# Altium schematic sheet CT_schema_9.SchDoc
size 281 x 153 mm
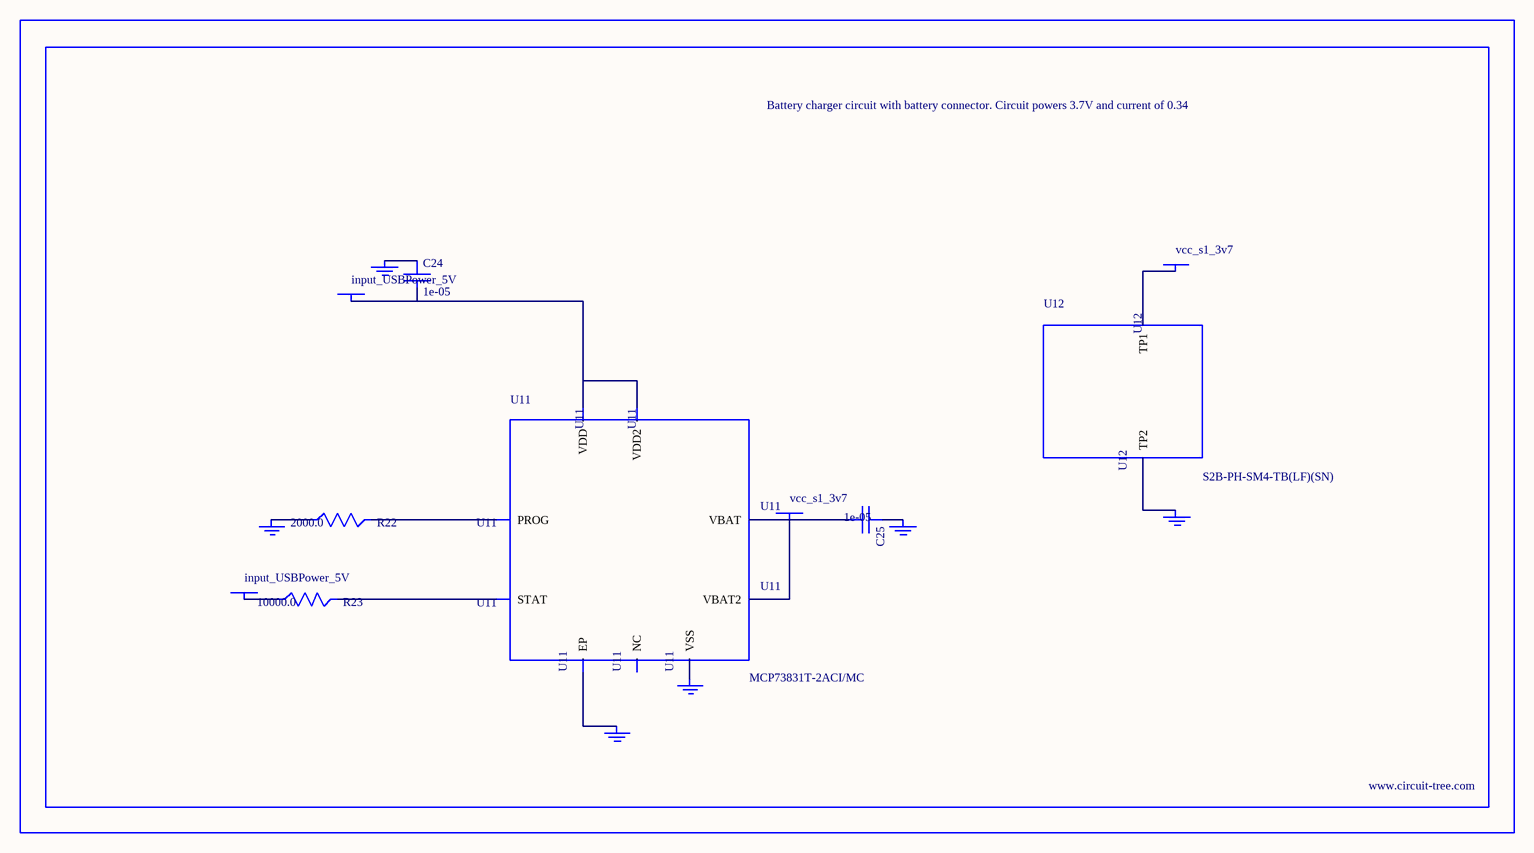
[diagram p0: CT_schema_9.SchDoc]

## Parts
BORDER8  (no value)
C24  1e-05  [C1206]
C25  1e-05  [C1206]
GND_INSTANCE_8_0  (no value)
GND_INSTANCE_8_1  (no value)
GND_INSTANCE_8_2  (no value)
GND_INSTANCE_8_3  (no value)
GND_INSTANCE_8_4  (no value)
GND_INSTANCE_8_5  (no value)
POWER_INSTANCE_8_0  input_USBPower_5V
POWER_INSTANCE_8_1  input_USBPower_5V
POWER_INSTANCE_8_2  vcc_s1_3v7
POWER_INSTANCE_8_3  vcc_s1_3v7
R22  2000.0  [R0603]
R23  10000.0  [R0603]
U11  MCP73831T-2ACI/MC  [DFN8_2X3MC]
U12  S2B-PH-SM4-TB(LF)(SN)  [JST-2-SMD]

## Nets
NetC24_1: C24.1 GND_INSTANCE_8_0.0(GND)
NetC24_2: C24.2 POWER_INSTANCE_8_0.0(PWR) U11.1(VDD) U11.2(VDD2)
NetC25_1: C25.1 GND_INSTANCE_8_1.0(GND)
NetC25_2: C25.2 POWER_INSTANCE_8_2.0(PWR) U11.3(VBAT) U11.4(VBAT2)
NetGND_INSTANCE_8_2_0: GND_INSTANCE_8_2.0(GND) R22.1
NetGND_INSTANCE_8_3_0: GND_INSTANCE_8_3.0(GND) U11.9(EP)
NetGND_INSTANCE_8_4_0: GND_INSTANCE_8_4.0(GND) U11.6(VSS)
NetGND_INSTANCE_8_5_0: GND_INSTANCE_8_5.0(GND) U12.2(TP2)
NetPOWER_INSTANCE_8_1_0: POWER_INSTANCE_8_1.0(PWR) R23.1
NetPOWER_INSTANCE_8_3_0: POWER_INSTANCE_8_3.0(PWR) U12.1(TP1)
NetR22_2: R22.2 U11.8(PROG)
NetR23_2: R23.2 U11.5(STAT)

Not connected (* = marked no-connect by the designer): U11 7(NC)

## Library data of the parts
BORDER8 = BORDER_PAGE8
C24 C25 = C1206C106K3RACTU
GND_INSTANCE_8_0-GND_INSTANCE_8_5 = GND
POWER_INSTANCE_8_0-POWER_INSTANCE_8_3 = PWR
R22 = RC0603JR-072KL
R23 = RC0603JR-0710KL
